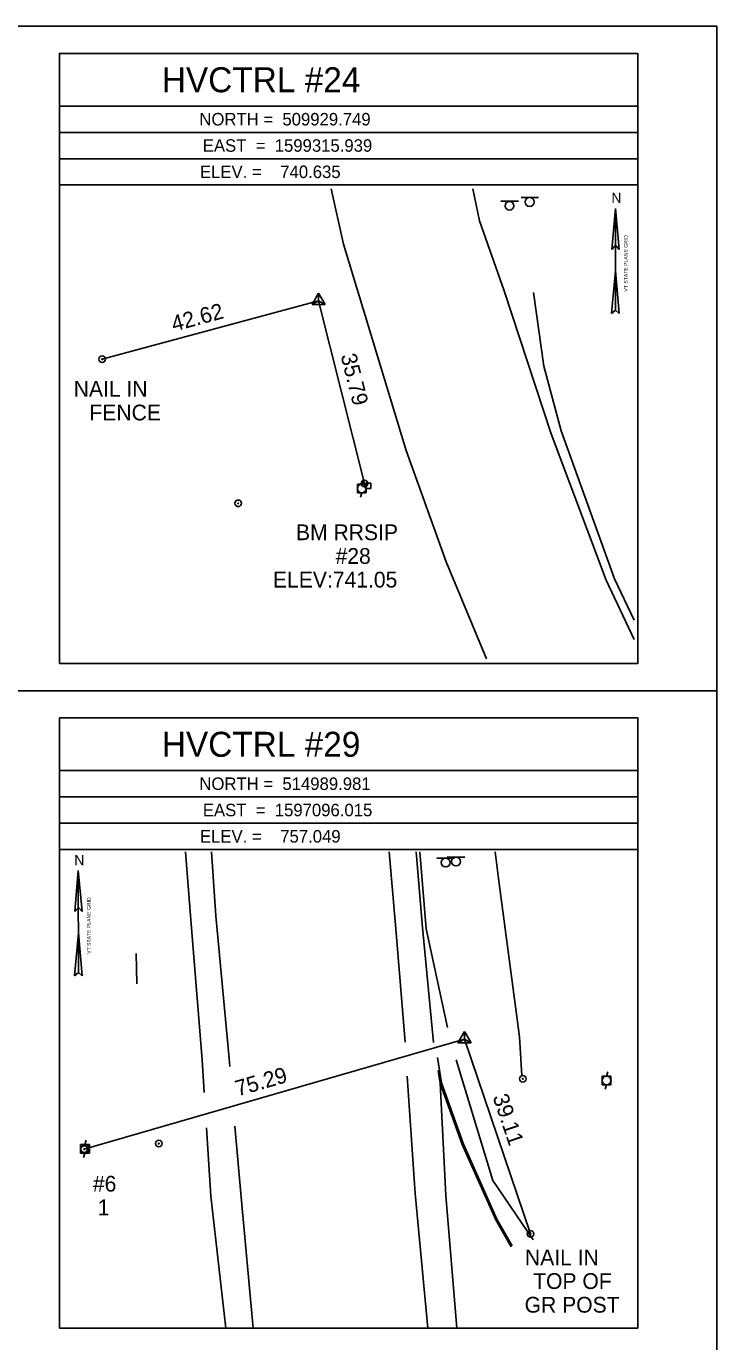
# Model space of a CAD drawing. Extents: x 1598730 to 1599370, y 501440 to 502728.
# Drawn here: x 1599238.2 to 1599369.5, y 501610.1 to 501860.2 of the extents above; entities that cross this region are included whole.
import ezdxf

# ---------------------------------------------------------------- set-up
doc = ezdxf.new("R2010")
doc.units = 0
for name, color, linetype in [('C_C', 7, 'Continuous'), ('CBP', 7, 'Continuous'), ('CPBM', 7, 'Continuous'), ('CPSM', 7, 'Continuous'), ('Default', 7, 'Continuous'), ('DHW', 7, 'Continuous'), ('LABL', 7, 'Continuous'), ('NBL1', 7, 'Continuous'), ('NBL2', 7, 'Continuous'), ('NNA_P', 7, 'Continuous'), ('PET', 7, 'Continuous'), ('PSP', 7, 'Continuous'), ('RC', 7, 'Continuous'), ('RDP', 7, 'Continuous'), ('RGR', 7, 'Continuous'), ('SSGN', 7, 'Continuous'), ('U_C', 7, 'Continuous'), ('UP', 7, 'Continuous'), ('UPGW', 7, 'Continuous')]:
    doc.layers.add(name, color=color, linetype=linetype)

msp = doc.modelspace()

# ---------------------------------------------------------------- linework, layer by layer
at = {"layer": 'CBP'}
for centre, radius in [((1599252.67, 501796.91), 0.625), ((1599252.67, 501796.91), 0.0833), ((1599302.55, 501773.29), 0.625), ((1599302.55, 501773.29), 0.0833), ((1599249.25, 501646.73), 0.625), ((1599249.25, 501646.73), 0.0833), ((1599334.12, 501630.61), 0.625), ((1599334.12, 501630.61), 0.0833)]:
    msp.add_circle(centre, radius, dxfattribs=at)
at = {"layer": 'CPBM'}
for p, q in [((1599302.75, 501772.35), (1599302.75, 501773.35)), ((1599302.75, 501773.35), (1599303.75, 501773.35)), ((1599303.75, 501772.35), (1599302.75, 501772.35)), ((1599303.25, 501772.85), (1599303.25, 501772.85)), ((1599303.25, 501772.85), (1599303.25, 501772.85)), ((1599303.75, 501773.35), (1599303.75, 501772.35))]:
    msp.add_line(p, q, dxfattribs=at)
at = {"layer": 'CPSM'}
for p, q in [((1599292.58, 501807.29), (1599293.83, 501809.45)), ((1599292.58, 501807.29), (1599293.83, 501808.01)), ((1599292.58, 501807.29), (1599295.08, 501807.29)), ((1599295.08, 501807.29), (1599293.83, 501809.45)), ((1599293.83, 501808.01), (1599293.83, 501809.45)), ((1599293.83, 501808.01), (1599293.83, 501808.01)), ((1599293.83, 501808.01), (1599295.08, 501807.29)), ((1599320.33, 501666.94), (1599321.58, 501669.11)), ((1599320.33, 501666.94), (1599321.58, 501667.66)), ((1599322.83, 501666.94), (1599321.58, 501669.11)), ((1599321.58, 501667.66), (1599321.58, 501669.11)), ((1599321.58, 501667.66), (1599321.58, 501667.66)), ((1599321.58, 501667.66), (1599322.83, 501666.94)), ((1599320.33, 501666.94), (1599322.83, 501666.94))]:
    msp.add_line(p, q, dxfattribs=at)
at = {"layer": 'Default'}
for p, q in [((1599252.67, 501796.91), (1599293.83, 501808.01)), ((1599293.83, 501808.01), (1599302.55, 501773.29)), ((1599249.25, 501646.73), (1599321.58, 501667.66)), ((1599321.58, 501667.66), (1599334.12, 501630.61))]:
    msp.add_line(p, q, dxfattribs=at)
at = {"layer": 'DHW'}
msp.add_lwpolyline([(1599259.13, 501683.91), (1599259.24, 501678.19)], dxfattribs=at)
at = {"layer": 'LABL'}
msp.add_lwpolyline([(1599332.49, 501660.73), (1599332.03, 501668.08), (1599328.03, 501698.21), (1599327.38, 501703.28)], dxfattribs=at)
at = {"layer": 'NBL1'}
msp.add_lwpolyline([(1598729.53, 501440.21), (1599369.53, 501440.21), (1599369.53, 501860.21), (1598729.53, 501860.21)], close=True, dxfattribs=at)
at = {"layer": 'NBL2'}
for p, q in [((1599354.53, 501845.04), (1599244.53, 501845.04)), ((1599354.53, 501840.04), (1599244.53, 501840.04)), ((1599354.53, 501835.04), (1599244.53, 501835.04)), ((1599354.53, 501830.04), (1599244.53, 501830.04)), ((1598729.53, 501733.88), (1599369.53, 501733.88)), ((1599354.53, 501718.71), (1599244.53, 501718.71)), ((1599354.53, 501713.71), (1599244.53, 501713.71)), ((1599354.53, 501708.71), (1599244.53, 501708.71)), ((1599354.53, 501703.71), (1599244.53, 501703.71))]:
    msp.add_line(p, q, dxfattribs=at)
for points in [[(1599244.53, 501739.04), (1599354.53, 501739.04), (1599354.53, 501855.04), (1599244.53, 501855.04)], [(1599244.53, 501612.71), (1599354.53, 501612.71), (1599354.53, 501728.71), (1599244.53, 501728.71)]]:
    msp.add_lwpolyline(points, close=True, dxfattribs=at)
at = {"layer": 'NNA_P'}
for p, q in [((1599349.57, 501817.8), (1599350.27, 501825.6)), ((1599350.27, 501806.22), (1599350.27, 501825.6)), ((1599350.96, 501817.8), (1599350.27, 501825.6)), ((1599349.57, 501817.8), (1599350.27, 501818.57)), ((1599350.96, 501817.8), (1599350.27, 501818.57)), ((1599350.27, 501813.75), (1599349.55, 501805.58)), ((1599350.27, 501813.75), (1599350.99, 501805.58)), ((1599350.27, 501806.22), (1599349.55, 501805.58)), ((1599350.27, 501806.22), (1599350.99, 501805.58)), ((1599247.44, 501691.89), (1599248.13, 501699.68)), ((1599248.14, 501680.31), (1599248.13, 501699.68)), ((1599248.83, 501691.89), (1599248.13, 501699.68)), ((1599247.44, 501691.89), (1599248.14, 501692.66)), ((1599248.83, 501691.89), (1599248.14, 501692.66)), ((1599248.14, 501687.84), (1599247.42, 501679.67)), ((1599248.14, 501687.84), (1599248.86, 501679.67)), ((1599248.14, 501680.31), (1599247.42, 501679.67)), ((1599248.14, 501680.31), (1599248.86, 501679.67))]:
    msp.add_line(p, q, dxfattribs=at)
at = {"layer": 'PET'}
for points in [[(1599325.73, 501739.95), (1599318.07, 501758.4), (1599310.5, 501779.57), (1599298.58, 501818.79), (1599296.2, 501829.31)], [(1599353.82, 501743.65), (1599348.51, 501754.9), (1599338.04, 501782.75), (1599329.12, 501809.93), (1599324.45, 501823.21), (1599323.17, 501829.31)], [(1599273.47, 501703.28), (1599274.27, 501691.09)], [(1599310.26, 501667.05), (1599308.49, 501688.65), (1599307.22, 501703.28)], [(1599276.93, 501662.46), (1599276.8, 501663.97), (1599274.27, 501691.09)], [(1599314.59, 501612.71), (1599312.19, 501638.31), (1599310.69, 501660.62)], [(1599281.35, 501612.71), (1599279.05, 501638.29), (1599277.92, 501651.13)]]:
    msp.add_lwpolyline(points, dxfattribs=at)
at = {"layer": 'PSP'}
for points in [[(1599268.51, 501703.28), (1599269.53, 501690.32)], [(1599315.65, 501667.01), (1599313.59, 501688.85), (1599312.41, 501703.28)], [(1599272.09, 501657.49), (1599271.69, 501663.71), (1599269.53, 501690.32)], [(1599320.11, 501612.71), (1599317.99, 501637.94), (1599316.94, 501659.25), (1599316.57, 501661.66)], [(1599276.18, 501612.71), (1599273.34, 501637.82), (1599272.52, 501650.77)]]:
    msp.add_lwpolyline(points, dxfattribs=at)
at = {"layer": 'RC'}
msp.add_lwpolyline([(1599330.65, 501628.32), (1599327.73, 501633.39), (1599321.36, 501647.67), (1599317.22, 501659.35), (1599316.41, 501664.13)], dxfattribs=at)
at = {"layer": 'RDP'}
msp.add_lwpolyline([(1599330.45, 501628.19), (1599327.5, 501633.31), (1599321.14, 501647.61), (1599316.94, 501659.25)], dxfattribs=at)
at = {"layer": 'RGR'}
for points in [[(1599353.82, 501747.3), (1599350.11, 501755.15), (1599339.95, 501783.27), (1599336.68, 501795.58), (1599334.68, 501809.6)], [(1599318.36, 501669.89), (1599314.3, 501688.64), (1599313.05, 501703.28)], [(1599334.66, 501629.47), (1599326.97, 501640.77), (1599319.99, 501663.71)]]:
    msp.add_lwpolyline(points, dxfattribs=at)
at = {"layer": 'SSGN'}
for p, q in [((1599332.32, 501827.64), (1599335.66, 501827.64)), ((1599328.49, 501826.94), (1599331.82, 501826.94)), ((1599330.13, 501826.1), (1599330.13, 501826.1)), ((1599333.97, 501826.81), (1599333.97, 501826.81)), ((1599318.3, 501702.24), (1599321.63, 501702.24)), ((1599316.34, 501702.04), (1599319.67, 501702.04)), ((1599317.99, 501701.21), (1599317.99, 501701.21)), ((1599319.95, 501701.4), (1599319.95, 501701.4))]:
    msp.add_line(p, q, dxfattribs=at)
for centre in [(1599333.97, 501826.81), (1599330.13, 501826.1), (1599319.95, 501701.4), (1599317.99, 501701.21)]:
    msp.add_circle(centre, 0.833, dxfattribs=at)
at = {"layer": 'UP'}
for p, q in [((1599301.2, 501771.51), (1599301.2, 501773.18)), ((1599301.2, 501773.18), (1599302.87, 501773.18)), ((1599302.28, 501774.01), (1599302.03, 501773.18)), ((1599302.03, 501772.34), (1599302.03, 501772.34)), ((1599302.87, 501773.18), (1599302.87, 501771.51)), ((1599302.87, 501771.51), (1599301.2, 501771.51)), ((1599301.78, 501770.68), (1599302.03, 501771.51)), ((1599347.77, 501658.96), (1599347.77, 501660.63)), ((1599347.77, 501660.63), (1599349.43, 501660.63)), ((1599348.85, 501661.46), (1599348.6, 501660.63)), ((1599348.6, 501659.8), (1599348.6, 501659.8)), ((1599349.43, 501660.63), (1599349.43, 501658.96)), ((1599349.43, 501658.96), (1599347.77, 501658.96)), ((1599348.35, 501658.13), (1599348.6, 501658.96)), ((1599248.56, 501645.95), (1599248.56, 501647.62)), ((1599248.56, 501647.62), (1599250.23, 501647.62)), ((1599249.64, 501648.45), (1599249.39, 501647.62)), ((1599250.23, 501647.62), (1599250.23, 501645.95)), ((1599250.23, 501645.95), (1599248.56, 501645.95)), ((1599249.14, 501645.12), (1599249.39, 501645.95)), ((1599249.39, 501646.79), (1599249.39, 501646.79))]:
    msp.add_line(p, q, dxfattribs=at)
for centre in [(1599302.03, 501772.34), (1599348.6, 501659.8), (1599249.39, 501646.79)]:
    msp.add_circle(centre, 0.833, dxfattribs=at)
at = {"layer": 'UPGW'}
for centre, radius in [((1599278.55, 501769.52), 0.625), ((1599278.55, 501769.52), 0.0833), ((1599332.68, 501660.12), 0.625), ((1599332.68, 501660.12), 0.0833), ((1599263.42, 501647.79), 0.625), ((1599263.42, 501647.79), 0.0833)]:
    msp.add_circle(centre, radius, dxfattribs=at)

# ---------------------------------------------------------------- texts
at = {"layer": 'C_C'}
for s, p in [('NAIL IN', (1599247.25, 501789.78)), ('FENCE', (1599250.24, 501785.28)), ('NAIL IN ', (1599333.07, 501624.65)), ('TOP OF', (1599334.63, 501620.15)), ('GR POST', (1599333.01, 501615.65))]:
    msp.add_text(s, height=3, dxfattribs=at).set_placement(p)
at = {"layer": 'Default'}
for s, rotation, p in [('42.62', 15.0976, (1599266.3, 501802.14)), ('35.79', 284.092, (1599297.99, 501797.61)), ('75.29', 16.1386, (1599278.46, 501656.75)), ('39.11', 288.6933, (1599326.89, 501656.67))]:
    msp.add_text(s, height=3, rotation=rotation, dxfattribs=at).set_placement(p)
at = {"layer": 'NBL2'}
for s, height, p in [('     HVCTRL #24    ', 4.75, (1599255.18, 501847.67)), ('NORTH =  509929.749 ', 2.375, (1599271.15, 501841.36)), ('EAST  =  1599315.939', 2.375, (1599271.8, 501836.36)), ('ELEV. =    740.635  ', 2.375, (1599271.26, 501831.36)), ('     HVCTRL #29    ', 4.75, (1599255.18, 501721.33)), ('NORTH =  514989.981 ', 2.375, (1599271.15, 501715.02)), ('EAST  =  1597096.015', 2.375, (1599271.81, 501710.02)), ('ELEV. =    757.049  ', 2.375, (1599271.26, 501705.02))]:
    msp.add_text(s, height=height, dxfattribs=at).set_placement(p)
at = {"layer": 'NNA_P'}
for p in [(1599349.51, 501826.61), (1599247.37, 501700.7)]:
    msp.add_text('N', height=1.97, dxfattribs=at).set_placement(p)
for p in [(1599352.62, 501809.78), (1599250.49, 501683.87)]:
    msp.add_text('VT STATE PLANE GRID', height=0.7, rotation=90.0204, dxfattribs=at).set_placement(p)
at = {"layer": 'U_C'}
for s, p in [('BM RRSIP', (1599289.53, 501762.51)), ('#28', (1599297.05, 501758.01)), ('ELEV:741.05', (1599285.15, 501753.51)), ('#6', (1599250.9, 501638.66)), ('1', (1599251.82, 501634.16))]:
    msp.add_text(s, height=3, dxfattribs=at).set_placement(p)

doc.saveas('drawing.dxf')
